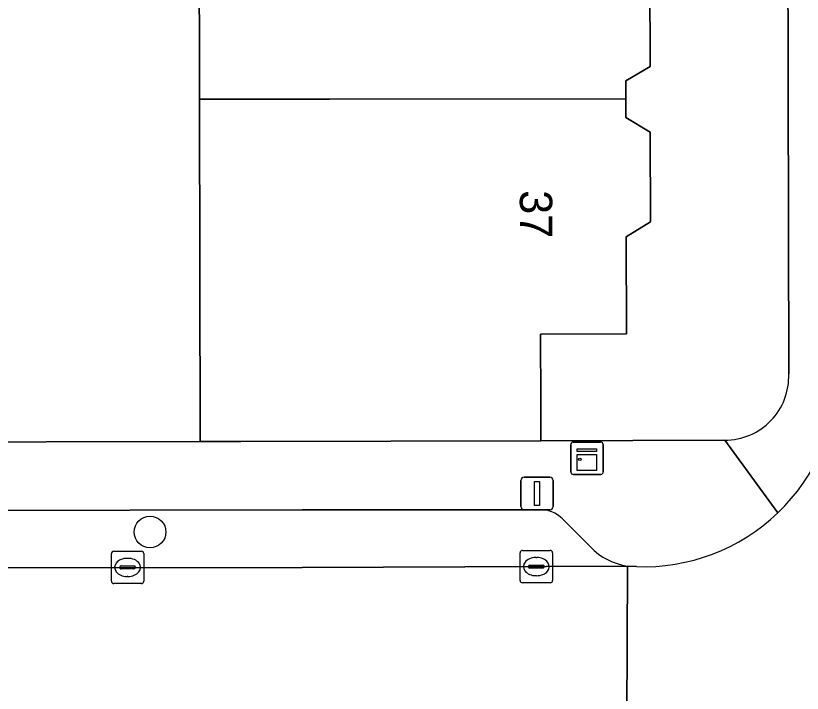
# Model space of a CAD drawing. Extents: x 160455 to 162082, y 388339 to 389736.
# Drawn here: x 160991.16 to 161015.44, y 388623.81 to 388644.74 of the extents above; entities that cross this region are included whole.
import ezdxf

# ---------------------------------------------------------------- set-up
doc = ezdxf.new("R2010")
doc.units = 0
for name, color, linetype in [('IMGEO_Boom', 7, 'Continuous'), ('IMGEO_Erf', 7, 'Continuous'), ('IMGEO_Kast', 7, 'Continuous'), ('IMGEO_Kolk', 7, 'Continuous'), ('IMGEO_Lichtmast', 7, 'Continuous'), ('IMGEO_Muur', 7, 'Continuous'), ('IMGEO_Pand', 7, 'Continuous'), ('IMGEO_Pand_nummerreeks', 7, 'Continuous'), ('IMGEO_Parkeervlak_open', 7, 'Continuous'), ('IMGEO_Rijbaan_lokaal_open', 7, 'Continuous'), ('IMGEO_Voetpad_open', 7, 'Continuous')]:
    doc.layers.add(name, color=color, linetype=linetype)

msp = doc.modelspace()

# ---------------------------------------------------------------- linework, layer by layer
at = {"layer": 'IMGEO_Boom'}
msp.add_circle((160995.308, 388628.79), 0.489, dxfattribs=at)
at = {"layer": 'IMGEO_Erf'}
for points in [[(161015.021, 388633.677), (161014.902, 388687.658)], [(160946.205, 388631.457), (160987.335, 388631.563), (160996.857, 388631.585), (160996.836, 388642.156), (160996.815, 388652.637), (160997.484, 388652.641), (161000, 388652.655), (161007.873, 388652.697), (161007.891, 388649.403), (161009.981, 388649.396), (161009.987, 388646.397), (161010.738, 388645.949), (161010.744, 388643.169), (161009.995, 388642.727), (161009.996, 388642.173), (161009.997, 388641.597), (161010.748, 388641.139), (161010.754, 388638.369), (161010.005, 388637.907), (161010.01, 388634.909), (161007.361, 388634.904), (161007.366, 388632.785), (161007.367, 388631.604), (161013.045, 388631.629)]]:
    msp.add_lwpolyline(points, dxfattribs=at)
msp.add_arc((161013.054, 388633.598), 1.969, 269.7374, 2.3127, dxfattribs=at)
at = {"layer": 'IMGEO_Kast'}
for p, q in [((161008.295, 388630.645), (161008.295, 388631.486)), ((161008.295, 388631.486), (161008.295, 388630.645)), ((161008.37, 388631.57), (161009.211, 388631.57)), ((161009.211, 388631.57), (161008.37, 388631.57)), ((161009.295, 388631.495), (161009.295, 388630.654)), ((161009.295, 388630.654), (161009.295, 388631.495)), ((161009.22, 388630.57), (161008.379, 388630.57)), ((161008.379, 388630.57), (161009.22, 388630.57))]:
    msp.add_line(p, q, dxfattribs=at)
for points in [[(161008.49, 388631.36), (161009.09, 388631.36), (161009.09, 388631.275), (161008.49, 388631.275), (161008.49, 388631.36)], [(161008.49, 388631.185), (161009.09, 388631.185), (161009.09, 388630.696), (161008.49, 388630.696), (161008.49, 388631.185)]]:
    msp.add_lwpolyline(points, dxfattribs=at)
msp.add_circle((161008.574, 388631.034), 0.0377, dxfattribs=at)
for centre, start, end in [((161008.373, 388631.492), 92.4484, 184.2845), ((161008.373, 388631.492), 92.4484, 184.2845), ((161009.217, 388631.492), 2.4484, 94.2845), ((161009.217, 388631.492), 2.4484, 94.2845), ((161008.373, 388630.648), 182.4484, 274.2845), ((161008.373, 388630.648), 182.4484, 274.2845), ((161009.217, 388630.648), 272.4484, 4.2845), ((161009.217, 388630.648), 272.4484, 4.2845)]:
    msp.add_arc(centre, 0.0779, start, end, dxfattribs=at)
at = {"layer": 'IMGEO_Kolk'}
for p, q in [((160994.113, 388627.273), (160994.113, 388628.125)), ((160994.188, 388628.199), (160995.04, 388628.199)), ((160995.114, 388628.125), (160995.114, 388627.273)), ((161006.73, 388627.297), (161006.73, 388628.149)), ((161006.805, 388628.223), (161007.657, 388628.223)), ((161007.731, 388628.149), (161007.731, 388627.297)), ((160994.601, 388627.979), (160994.626, 388627.979)), ((161007.218, 388628.003), (161007.243, 388628.003)), ((160994.372, 388627.693), (160994.372, 388627.705)), ((160994.81, 388627.656), (160994.412, 388627.656)), ((160994.415, 388627.742), (160994.813, 388627.742)), ((160994.856, 388627.705), (160994.856, 388627.693)), ((161006.989, 388627.717), (161006.989, 388627.729)), ((161007.427, 388627.68), (161007.029, 388627.68)), ((161007.032, 388627.766), (161007.43, 388627.766)), ((161007.473, 388627.729), (161007.473, 388627.717)), ((160994.624, 388627.419), (160994.599, 388627.419)), ((161007.241, 388627.443), (161007.216, 388627.443)), ((160995.04, 388627.199), (160994.188, 388627.199)), ((161007.657, 388627.223), (161006.805, 388627.223))]:
    msp.add_line(p, q, dxfattribs=at)
for points in [[(160994.113, 388627.273), (160994.113, 388628.125)], [(160994.188, 388628.199), (160995.04, 388628.199)], [(160995.114, 388628.125), (160995.114, 388627.273)], [(161006.73, 388627.297), (161006.73, 388628.149)], [(161006.805, 388628.223), (161007.657, 388628.223)], [(161007.731, 388628.149), (161007.731, 388627.297)], [(160995.04, 388627.199), (160994.188, 388627.199)], [(161007.657, 388627.223), (161006.805, 388627.223)]]:
    msp.add_lwpolyline(points, dxfattribs=at)
for centre, radius, start, end in [((160994.19, 388628.123), 0.0765, 91.552, 178.448), ((160994.19, 388628.123), 0.0765, 91.552, 178.448), ((160995.038, 388628.123), 0.0765, 1.552, 88.448), ((160995.038, 388628.123), 0.0765, 1.552, 88.448), ((161006.807, 388628.147), 0.0765, 91.552, 178.448), ((161006.807, 388628.147), 0.0765, 91.552, 178.448), ((161007.655, 388628.147), 0.0765, 1.552, 88.448), ((161007.655, 388628.147), 0.0765, 1.552, 88.448), ((160994.412, 388627.702), 0.0403, 85.8775, 175.7526), ((160994.409, 388627.692), 0.0366, 178.938, 274.7102), ((160994.813, 388627.699), 0.043, 264.8664, 352.4533), ((160994.817, 388627.704), 0.0386, 1.7309, 96.639), ((161007.029, 388627.726), 0.0403, 85.8775, 175.7526), ((161007.026, 388627.716), 0.0366, 178.938, 274.7102), ((161007.43, 388627.723), 0.043, 264.8664, 352.4533), ((161007.434, 388627.728), 0.0386, 1.7309, 96.639), ((161006.807, 388627.299), 0.0765, 181.552, 268.448), ((161006.807, 388627.299), 0.0765, 181.552, 268.448), ((161007.655, 388627.299), 0.0765, 271.552, 358.448), ((161007.655, 388627.299), 0.0765, 271.552, 358.448), ((160994.19, 388627.275), 0.0765, 181.552, 268.448), ((160994.19, 388627.275), 0.0765, 181.552, 268.448), ((160995.038, 388627.275), 0.0765, 271.552, 358.448), ((160995.038, 388627.275), 0.0765, 271.552, 358.448)]:
    msp.add_arc(centre, radius, start, end, dxfattribs=at)
for centre, major_axis, ratio, start_param, end_param in [((160994.6, 388627.699), (-0.387, 0.002), 0.722429, 4.712389, 7.853982), ((160994.625, 388627.699), (-0.39, 0.002), 0.717154, 1.570796, 4.712389), ((161007.217, 388627.723), (-0.387, 0.002), 0.722429, 4.712389, 7.853982), ((161007.242, 388627.723), (-0.39, 0.002), 0.717154, 1.570796, 4.712389)]:
    msp.add_ellipse(centre, major_axis=major_axis, ratio=ratio, start_param=start_param, end_param=end_param, dxfattribs=at)
at = {"layer": 'IMGEO_Lichtmast'}
for p, q in [((161006.857, 388630.481), (161007.647, 388630.481)), ((161007.647, 388630.481), (161006.857, 388630.481)), ((161006.757, 388629.581), (161006.757, 388630.381)), ((161006.757, 388630.381), (161006.757, 388629.581)), ((161007.747, 388630.381), (161007.747, 388629.581)), ((161007.747, 388629.581), (161007.747, 388630.381)), ((161007.647, 388629.481), (161006.857, 388629.481)), ((161006.857, 388629.481), (161007.647, 388629.481))]:
    msp.add_line(p, q, dxfattribs=at)
msp.add_lwpolyline([(161007.177, 388630.356), (161007.327, 388630.356), (161007.327, 388629.606), (161007.177, 388629.606), (161007.177, 388630.356)], dxfattribs=at)
for centre, start, end in [((161006.857, 388630.381), 90, 180), ((161006.857, 388630.381), 90, 180), ((161007.647, 388630.381), 0, 90), ((161007.647, 388630.381), 360, 90), ((161006.857, 388629.581), 180, 270), ((161006.857, 388629.581), 180, 270), ((161007.647, 388629.581), 270, 0), ((161007.647, 388629.581), 270, 0)]:
    msp.add_arc(centre, 0.1, start, end, dxfattribs=at)
at = {"layer": 'IMGEO_Muur'}
msp.add_lwpolyline([(160998.109, 388631.588), (160987.335, 388631.563)], dxfattribs=at)
at = {"layer": 'IMGEO_Pand'}
for points in [[(161009.981, 388649.396), (161007.891, 388649.403), (161007.873, 388652.697), (161000, 388652.655), (160997.484, 388652.641), (160996.815, 388652.637), (160996.836, 388642.156), (161000.85, 388642.161), (161009.996, 388642.173), (161009.995, 388642.727), (161010.744, 388643.169), (161010.738, 388645.949), (161009.987, 388646.397)], [(161010.005, 388637.907), (161010.754, 388638.369), (161010.748, 388641.139), (161009.997, 388641.597), (161009.996, 388642.173), (161000.85, 388642.161), (160996.836, 388642.156), (160996.857, 388631.585), (160998.109, 388631.588), (161007.367, 388631.604), (161007.366, 388632.785), (161007.361, 388634.904), (161010.01, 388634.909)]]:
    msp.add_lwpolyline(points, close=True, dxfattribs=at)
at = {"layer": 'IMGEO_Parkeervlak_open'}
for points in [[(161007.326, 388629.481), (161000, 388629.472), (160989.347, 388629.459), (160988.977, 388629.459), (160988.98, 388627.682), (161000, 388627.698), (161010.049, 388627.741)], [(161008.899, 388628.33), (161008.04, 388629.195)]]:
    msp.add_lwpolyline(points, dxfattribs=at)
for centre, radius, start, end in [((161007.358, 388628.526), 0.956, 44.4466, 91.8952), ((161010.325, 388629.696), 1.974, 223.7805, 261.9788)]:
    msp.add_arc(centre, radius, start, end, dxfattribs=at)
at = {"layer": 'IMGEO_Rijbaan_lokaal_open'}
msp.add_lwpolyline([(161010.049, 388627.741), (161000, 388627.698), (160988.98, 388627.682), (160982.007, 388627.672), (160969.838, 388627.654), (160963.828, 388627.645), (160957.279, 388627.635), (160957.285, 388623.088), (160964.363, 388623.096), (160970.439, 388623.102), (160983.144, 388623.116), (160989.379, 388623.123), (161000, 388623.134), (161010.022, 388623.066)], close=True, dxfattribs=at)
msp.add_lwpolyline([(161010.319, 388627.722), (161010.049, 388627.741), (161010.022, 388623.066), (161010.327, 388623.114), (161010.509, 388623.142)], dxfattribs=at)
for centre, radius, start, end in [((161010.542, 388633.712), 5.993, 313.7434, 359.6243), ((161010.537, 388633.717), 5.999, 267.9171, 313.7405)]:
    msp.add_arc(centre, radius, start, end, dxfattribs=at)
at = {"layer": 'IMGEO_Voetpad_open'}
for points in [[(161014.902, 388687.658), (161015.021, 388633.677)], [(161014.685, 388629.383), (161013.045, 388631.629), (161007.367, 388631.604), (160998.109, 388631.588), (160996.857, 388631.585), (160987.335, 388631.563), (160946.205, 388631.457), (160892.083, 388631.326), (160890.219, 388628.889)], [(161013.045, 388631.629), (161014.685, 388629.383)], [(160959.903, 388629.39), (160963.508, 388629.381), (160963.826, 388629.382), (160969.835, 388629.406), (160970.292, 388629.408), (160981.468, 388629.458), (160982.004, 388629.458), (160988.977, 388629.459), (160989.347, 388629.459), (161000, 388629.472), (161007.326, 388629.481)], [(161008.04, 388629.195), (161008.899, 388628.33)], [(161010.049, 388627.741), (161010.319, 388627.722)]]:
    msp.add_lwpolyline(points, dxfattribs=at)
for centre, radius, start, end in [((161013.054, 388633.598), 1.969, 269.7374, 2.3127), ((161010.542, 388633.712), 5.993, 313.7434, 359.6243), ((161007.358, 388628.526), 0.956, 44.4466, 91.8952), ((161010.537, 388633.717), 5.999, 267.9171, 313.7405), ((161010.325, 388629.696), 1.974, 223.7805, 261.9788)]:
    msp.add_arc(centre, radius, start, end, dxfattribs=at)

# ---------------------------------------------------------------- texts
at = {"layer": 'IMGEO_Pand_nummerreeks'}
msp.add_text('37', height=1, rotation=270.1144, dxfattribs=at).set_placement((161006.721, 388639.35))

doc.saveas('drawing.dxf')
